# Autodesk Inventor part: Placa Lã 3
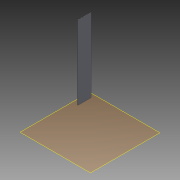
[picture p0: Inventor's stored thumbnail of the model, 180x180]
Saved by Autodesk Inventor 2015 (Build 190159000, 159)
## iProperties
Created: 2015-04
Part Number: Placa Lã 3
Material: Generic
Document SubType Name: Modeling
Designer: suporte
Density: 1 g/cm^3
Appearance: Default
Author: suporte
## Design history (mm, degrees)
workplane "Work Plane1"
sketch "Sketch1"
  geometry: L1 (-859.534, 500.6)-(-840.466, 500.6) reference; L2 (-859.534, 874.4)-(-840.466, 874.4) reference; L3 (-843.75, 874.4)-(-856.25, 874.4); L4 (-856.25, 874.4)-(-856.25, 500.6); L5 (-856.25, 500.6)-(-843.75, 500.6); L6 (-843.75, 500.6)-(-843.75, 874.4); 3 further points
  constraints: 8 end point, 2 midpoint, 2 parallel, 2 point on line, 1 coincident, 1 horizontal, 1 perpendicular
  dimensions: "d0" = 12.5 distance between parallel lines of L4 L6
extrude "Extrusion1" new body sketch "Sketch1" distance "d1" = 2100; taper "d2" = 0 deg
body "Solid1"
node "Reference1"
node "Reference2"
